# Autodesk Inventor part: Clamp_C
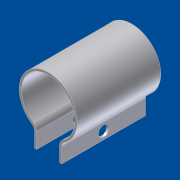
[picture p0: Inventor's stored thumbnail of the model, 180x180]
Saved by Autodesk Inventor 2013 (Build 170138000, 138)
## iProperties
Shininess: 64.0
Length Units: 11269
Angle Units: 11279
Time Units: 11290
Mass Units: 11283
Length Display Precision: 3
Angle Display Precision: 2
Compacted: True
Part Number: Clamp_C
Document SubType Name: Sheet Metal
Created: 2002-10
Designer: roithn
Density: 1 g/cm^3
Sheet Metal Rule: Default
Material: Generic
Density: 0.0
Volumn: 0.0
Area: 0.0
PropertySet Name: Model Information
Control State: 0
Master: False
Checked Out: False
Author: roithn
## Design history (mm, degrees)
node "Contour Flange1"
  sketch "Sketch1"
    geometry: L1 (20.463, -76.976)-(20.463, -86.976); L2 (12.963, -58.268)-(12.963, -40.768); L3 (5.463, -76.976)-(5.463, -86.976); A1 r 17.5 centre (12.963, -58.268) between (22.685, -72.819) and (3.241, -72.819); A2 r 5 centre (25.463, -76.976) between (22.685, -72.819) and (20.463, -76.976); A3 r 5 centre (0.463, -76.976) between (5.463, -76.976) and (3.241, -72.819)
    constraints: 7 point on circle, 6 end point, 4 tangent, 3 centre point, 1 equal radius, 1 parallel, 1 symmetric about line, 1 vertical, 1 other
    dimensions: "d0" = 35 diameter of A1; "d1" = 5 radius of A2; "d2" = 10 distance of L1.start L1.end; "d21" = 7.5 distance between parallel lines of L1 L2
sketch "Sketch2"
  geometry: 3 further points
  dimensions: "d10" = 27.5 horizontal distance of point (27.5, 5) point (55, 0) (= 0.5 x d3); "d11" = 5 vertical distance of point (0, 0) point (27.5, 5) (= 0.5 x d2)
hole "Hole1" sketch "Sketch2" at (27.5, 5) diameter "d12" = 7; stored, may be unused: countersink angle "d16" = 82 deg, drill point angle "d18" = 118 deg; dims "d13" = 6, "d14" = 4, "d15" = 2, "d17" = 8
body "Solid1"
face "Plate1" dims "d3" = 55, "d4" = 1.5 (= BendReliefWidth), "d6" = 3 (= MinimumRemnant), "d8" = 1.5 (= BendRadius), "d9" = 0.5, "Thickness" = 1.5
bend "Bend1" dims "d4" = 1.5 (= BendReliefWidth), "d5" = 0.75 (= BendReliefDepth), "d6" = 3 (= MinimumRemnant), "d7" = 1.5 (= BendRadius), "d8" = 1.5 (= BendRadius), "d9" = 0.5, "SeamGap" = 0.01, "Thickness" = 1.5
other parameters: "BendRadius" = 1.5 (= Thickness), "BendReliefWidth" = 1.5 (= Thickness), "BendReliefDepth" = 0.75 (= 0.5 x Thickness), "CornerReliefSize" = 6 (= 4 x Thickness), "MinimumRemnant" = 3 (= 2 x Thickness), "TransitionRadius" = 1.5 (= BendRadius), "d19" = 0, "d20" = 0, "JacobiRadiusSize" = 1.5 (= Thickness), "GapSize" = 1.5 (= Thickness)
